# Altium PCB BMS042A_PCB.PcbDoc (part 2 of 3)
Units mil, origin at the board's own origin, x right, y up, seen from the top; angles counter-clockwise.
Board outline 4409.45 x 3307 mil, 6 copper layers (Top Layer, Layer 2 - PGND, Layer 3, Layer 4, Layer 5 - PGND, Bottom Layer), stack 60.8 mil thick; 273 components, 77 nets, 544 pads, 927 vias.
Unrouted connection lines stored in the file: 219.
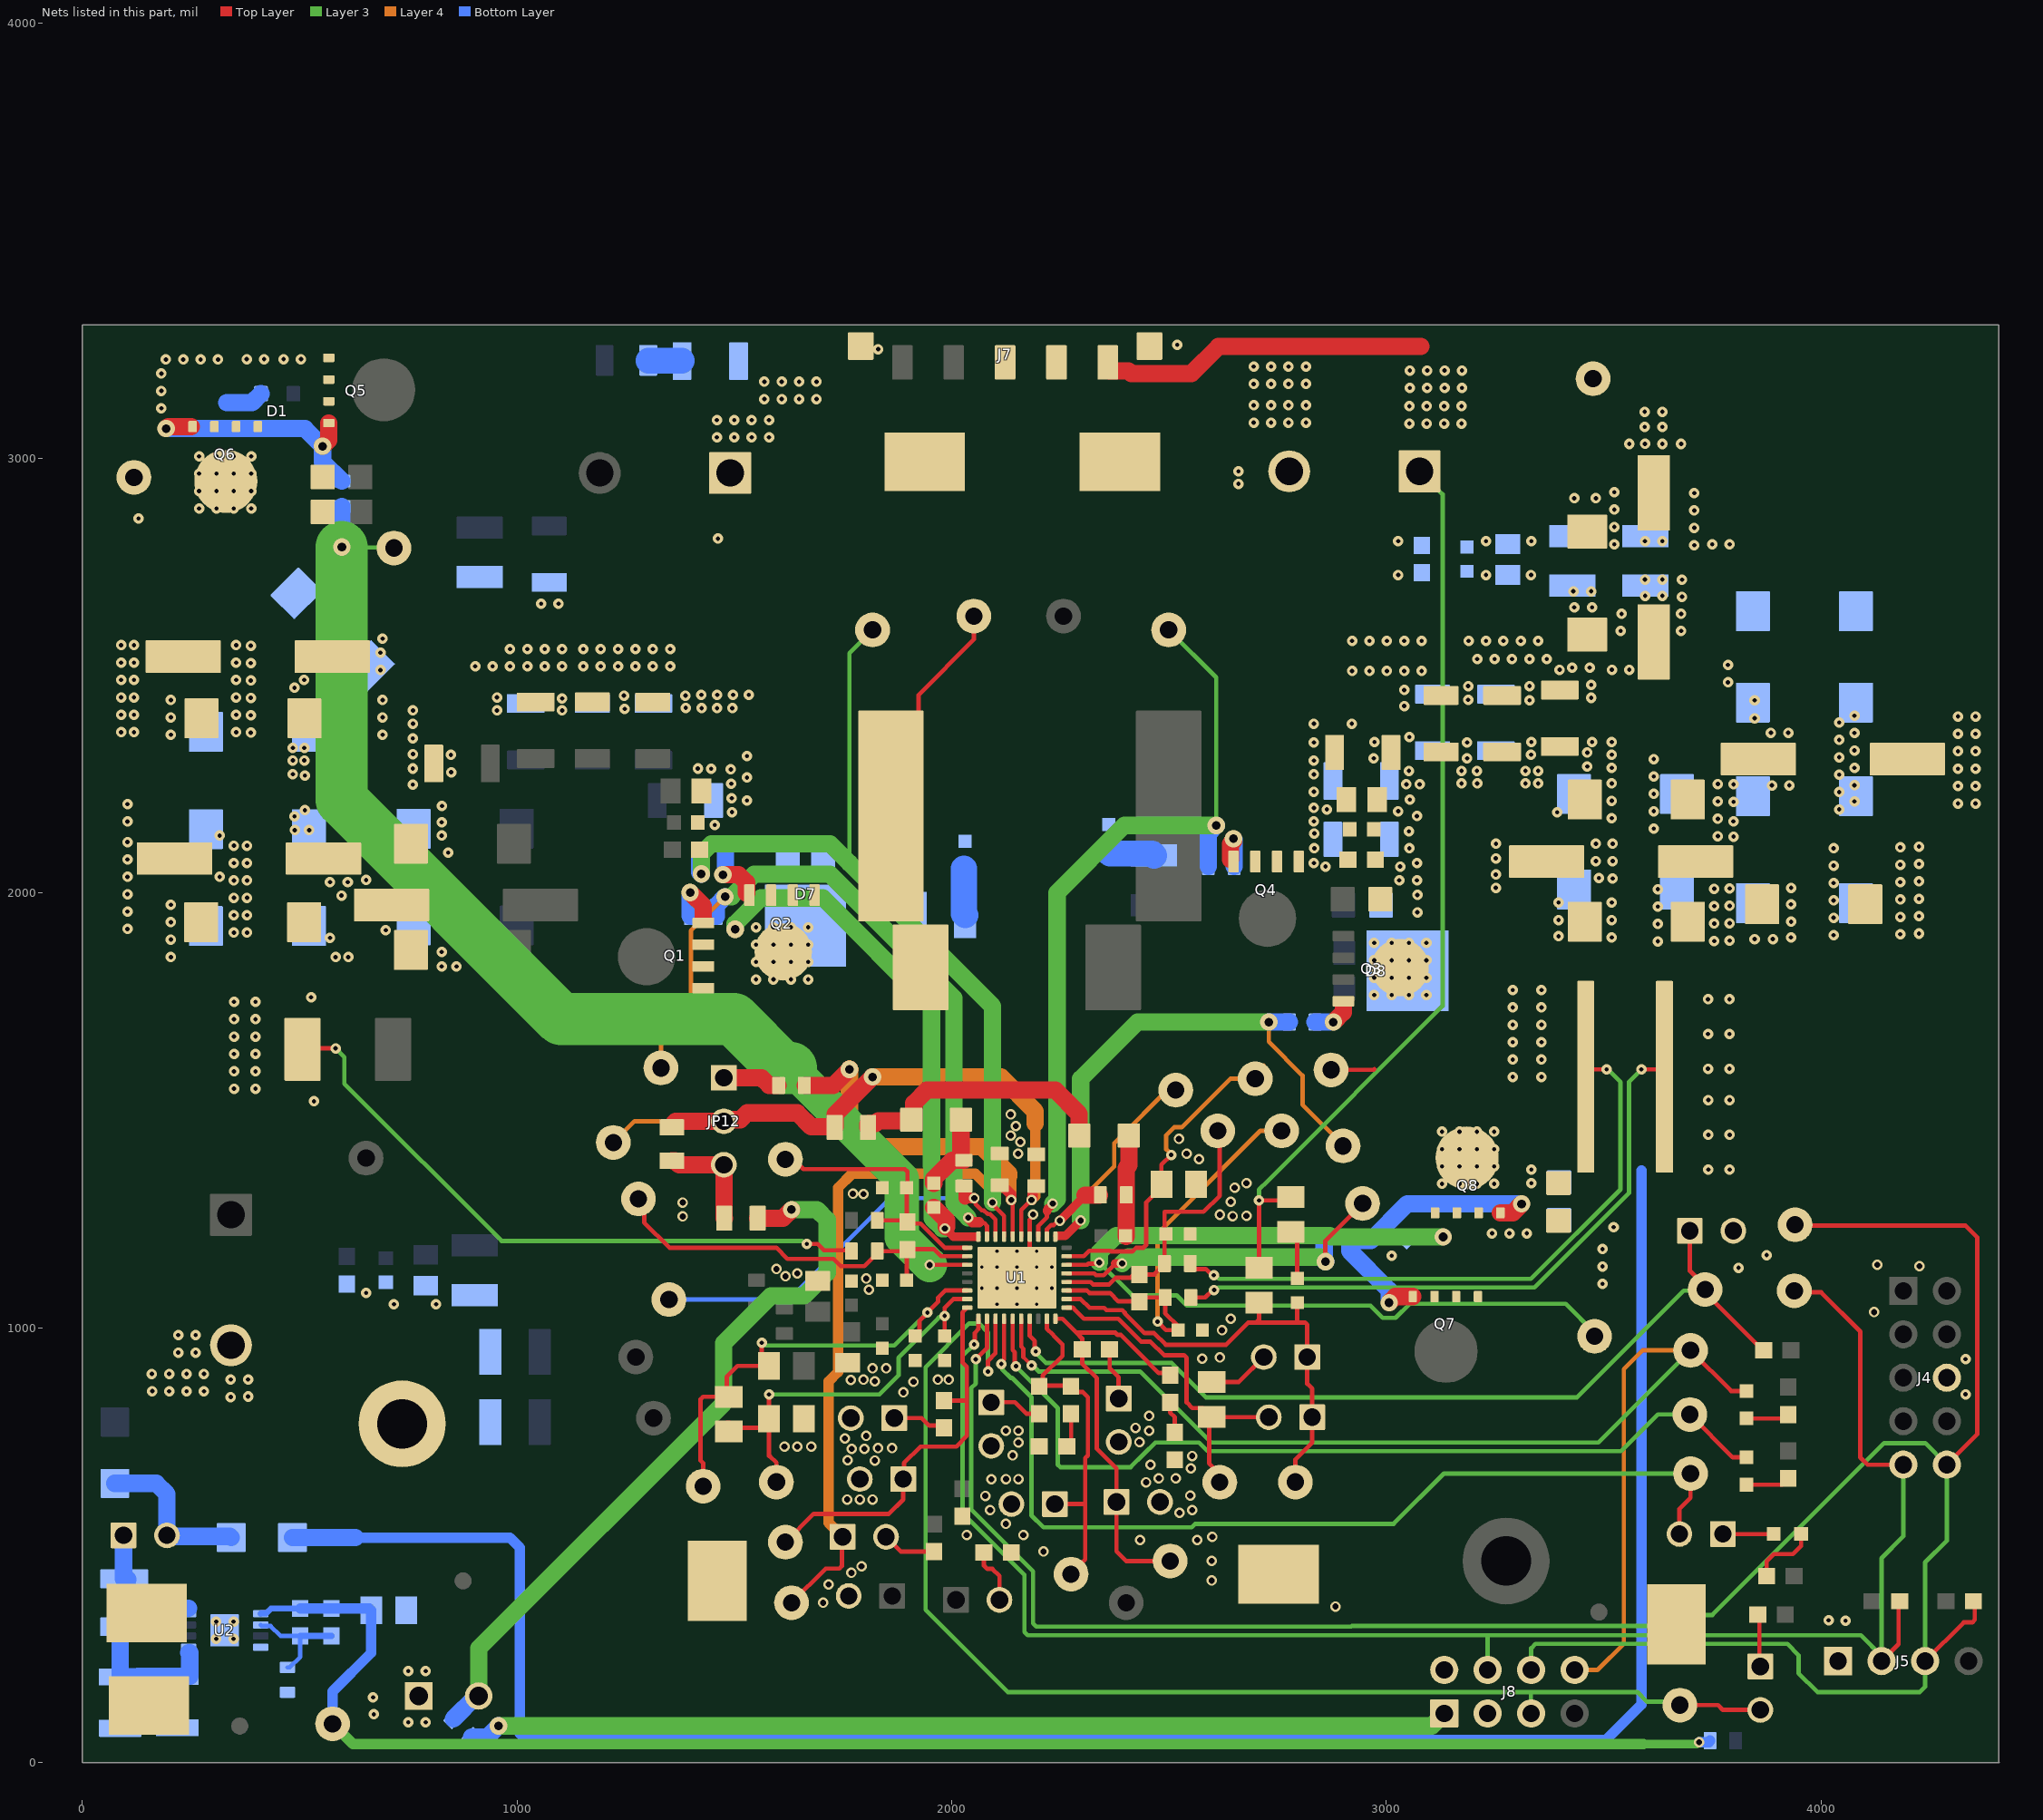
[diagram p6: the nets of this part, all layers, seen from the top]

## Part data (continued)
J7: library part CMP-0097332-1, "Conn Board to Board HDR 5 POS 3mm Solder RA SMD T/R", Current_A=5A, Digikey Part Number=478-109159005101916CT-ND, Manufacturer="KYOCERA AVX", Mouser Part Number=581-109159005101916, Operating Temperature Range="-40°C to +125°C", Voltage_V=125V
J8: library part CMP-0075408-3, "Header, 100mil, 4x2, Gold, TH", Color=Black, Current_A=6.3A, Manufacturer=Samtec, Supplier Part Number 1=SAM1028-04-ND, Voltage_V=550V
JP1 JP2 JP13 JP14 JP15: library part CMP-0002337-1, "Header, 100mil, 2x1, Tin, TH", Color=Black, Current_A=3A, Manufacturer="Sullins Connector Solutions", Supplier Part Number 1=S1012E-02-ND, Voltage_V=1.8kV
JP3 JP4 JP5 JP6 JP7 JP8 JP9 JP10 JP11 JP16: library part CMP-0002337-1, "Header, 100mil, 2x1, Tin, TH", Color=Black, Current_A=3A, Manufacturer="Sullins Connector Solutions", PartNumber=PEC02SAAN, Supplier Part Number 1=S1012E-02-ND, Voltage_V=1.8kV
JP12: library part CMP-0002338-1, "Header, 100mil, 3x1, Tin, TH", Color=Black, Current_A=3A, Manufacturer="Sullins Connector Solutions", Supplier Part Number 1=S1012E-03-ND, Voltage_V=1.8kV
L1: library part CMP-0093259-1, "Commercial Inductors, High Saturation Series 10uH 16.5A 12mΩ 20%", Manufacturer=Vishay, Operating Temperature Range="-55°C to +125°C", Test Frequency=100kHz, Tolerance_%=20%
L2: library part CMP-0096007-1, "Power Choke Coil 10uH 20% 9A 22mOhm", Manufacturer=Cyntec, Operating Temperature Range="-55°C to +125°C", Test Frequency=100kHz, Tolerance_%=20%
LBL1: library part CMP-0003625-1, "Thermal Transfer Printable Labels, 0.650\" W x 0.200\" H - 10,000 per roll", Manufacturer=Brady, Supplier Part Number 1=97C5133
LOGO1: library part CMP-0074835-1, "IEC 61010-1 High Voltage Warning"
LOGO2: library part CMP-0074837-2, "IEC 61010-1 Hot Surface Warning", Manufacturer="Texas Instruments"
LOGO3: library part CMP-0074836-1, "IEC 61010-1 Caution Warning"
LOGO5: library part CMP-0074844-1
LOGO6: library part CMP-0074847-1, "FCC_disclaimer"
LOGO7: library part CMP-0074769-1
Q1 Q2 Q3 Q4: library part CMP-0096839-1, "N-Channel 80 V 18.6A (Ta), 70.6A (Tc) 5W (Ta), 71.4W (Tc) Surface Mount PowerPAK® SO-8", Digikey Part Number=742-SIR880BDP-T1-RE3CT-ND, Drain To Source Breakdown Voltage=80V, Input Capacitace At Vds="2930pF @ 40V", Manufacturer=Vishay, Mouser Part Number=78-SIR880BDP-T1-RE3, Operating Temperature Range="-55°C to +150°C", Power_W=5W, Pulse Drain Current=200A, Typ Forward Diode Voltage=0.74V
Q5 Q6 Q7 Q8: library part CMP-0093242-3, "100V N-Channel MOSFET, DFN5x6-8L, RoHS", Drain To Source Breakdown Voltage=100V, Input Capacitace At Vds="5940pF @ 50V", Manufacturer="Alpha & Omega Semiconductor", Operating Temperature Range="-55°C to +150°C", Power_W=6.2W, Pulse Drain Current=320A, Typ Forward Diode Voltage=0.68V
R2: library part CMP-0096841-1, "Res Metal Strip 2512 0.005 Ohm 1% 1W 110ppm/C Molded SMD SMD Embossed Plastic T/R", Digikey Part Number=WSLG-.005CT-ND, Manufacturer=Vishay, Mouser Part Number=71-WSL25125L000FEA, Octopart Part Number=dd8716d1bbbb0240, Operating Temperature Range="-65°C to +170°C", Power_W=1W, TempCo=110ppm/°C, Tolerance_%=1%
R3 R8 R9 R12 R13 R17 R20 R23 R68 R69 R100 R101 R160: library part CMP-0093629-1, "Thick Film Resistors - SMD 1/10watt ZEROohm Jumper", Manufacturer=Vishay, Operating Temperature Range="-55°C to +155°C", Power=250mW, Power_W=330mW, TempCo=100ppm/°C, Tolerance_%=1%
R5 R6 R22 R25: library part CMP-0093685-1, "RES Thick Film, 10Ω, 1%, 0.1W, 100ppm/°C, 0603", Approved Alternate Part Number=541-1.00HHCT-ND, Manufacturer=Vishay, Operating Temperature Range="-55°C to +155°C", Power=100mW, TempCo=100ppm/°C, Tolerance_%=1%, Voltage=75V
R10: library part CMP-0093410-1, "RES Thick Film, 10Ω, 1%, 0.75W, 100ppm/°C, 1206", Manufacturer="Vishay Dale", Operating Temperature Range="-55°C to +155°C", Power_W=750mW, TempCo=100ppm/°C, Tolerance_%=1%
R14 R15: library part CMP-0015022-3, "RES, 3.30, 1%, 0.75 W, AEC-Q200 Grade 0, 1210", Manufacturer=Vishay-Dale, Power_W=750mW, Supplier Part Number 1=541-3.30DCT-ND, TempCo="100 ppm/C", Tolerance_%=1%, Value2=0.75W, Value_Code=3R30, ValueDisplayed=3.30
R21: library part CMP-0021522-3, "Thick Film Resistors - SMD 1/8Watt 1Mohms 1% Commercial Use", Manufacturer="Vishay / Dale", Power_W=125mW, Supplier Part Number 1=P1.00MCCT-ND, TempCo="100 ppm/C", Tolerance_%=1%, Value2=0.125W, Value_Code=1M00, ValueDisplayed=1.00M
R24: library part CMP-0093177-1, "5 mOhms ±1% 5W Chip Resistor Wide 4320 (11050 Metric), 2043 Current Sense, Moisture Resistant Metal Foil", Digikey Part Number=FCSL110R005FERCT-ND, Manufacturer=Ohmite, Mouser Part Number=588-FCSL110R005FER, Operating Temperature Range="-55°C to +155°C", Power_W=5W, TempCo=50ppm/°C, Tolerance_%=1%
R27: library part CMP-0021561-3, "RES, 133 k, 1%, 0.125 W, AEC-Q200 Grade 0, 0805", Manufacturer=Panasonic, Power_W=125mW, Supplier Part Number 1=P133KCCT-ND, TempCo="100 ppm/C", Tolerance_%=1%, Value2=0.125W, Value_Code=133k
R28: library part CMP-0018933-2, "Thick Film Resistors - SMD 0805 Anti-Surge Res. 0.1%, 249Kohm", Manufacturer=Panasonic, Power_W=125mW, Supplier Part Number 1=RG20P249KBCT-ND, TempCo="25 ppm/C", Tolerance_%=0.1%, Value2=0.125W, Value_Code=249k
R30: library part CMP-0021646-3, "RES, 25.5 k, 1%, 0.125 W, AEC-Q200 Grade 0, 0805", Manufacturer=Panasonic, Power_W=125mW, Supplier Part Number 1=P25.5KCCT-ND, TempCo="100 ppm/C", Tolerance_%=1%, Value2=0.125W, Value_Code=25k5, ValueDisplayed=25.5k
R32: library part CMP-0021666-2, "RES, 3.00 k, 1%, 0.125 W, AEC-Q200 Grade 0, 0805", Manufacturer=Panasonic, Power_W=125mW, Supplier Part Number 1=P3.0KCCT-ND, TempCo="100 ppm/C", Tolerance_%=1%, Value2=0.125W, Value_Code=3k00, ValueDisplayed=3.00k
R34: library part CMP-0023199-5, "RES, 5.23 k, 1%, 0.1 W, 0603", Manufacturer=Yageo, Power_W=100mW, Supplier Part Number 1=311-5.23KHRCT-ND, TempCo="100 ppm/C", Tolerance_%=1%, Value2=0.1W, Value_Code=5k23, ValueDisplayed=5.23k
R36: library part CMP-0022038-4, "RES, 133 k, 1%, 0.1 W, AEC-Q200 Grade 0, 0603", Manufacturer=Vishay-Dale, Power_W=100mW, Supplier Part Number 1=541-133KHCT-ND, TempCo="100 ppm/C", Tolerance_%=1%, Value2=0.1W, Value_Code=133k
R41 R53 R54 R55 R56: library part CMP-0022746-5, "RES, 10.0 k, 1%, 0.1 W, 0603", Manufacturer=Yageo, Power_W=100mW, Supplier Part Number 1=311-10.0KHRCT-ND, TempCo="100 ppm/C", Tolerance_%=1%, Value2=0.1W, Value_Code=10k0, ValueDisplayed=10.0k
R45 R120: library part CMP-0092857-1, "Thick Film Resistors - SMD 1/8watt ZEROohm Jumper", Manufacturer=Vishay, Operating Temperature Range="-55°C to +155°C", Power_W=500mW, TempCo=200ppm/°C, Tolerance_%=5%
R46: library part CMP-0092853-1, "Thick Film Resistors - SMD 3/4watt 20ohms 1% High Power AEC-Q200", Manufacturer="Vishay Dale", Operating Temperature Range="-55°C to +155°C", Part Number=CRCW12104R30FKEAHP, Power_W=750mW, TempCo=100ppm/°C, Tolerance_%=1%
R48: library part CMP-0023140-4, "RES, 499 k, 1%, 0.1 W, 0603", Manufacturer=Yageo, Power_W=100mW, Supplier Part Number 1=311-499KHRCT-ND, TempCo="100 ppm/C", Tolerance_%=1%, Value2=0.1W, Value_Code=499k
R49: library part CMP-0093627-1, "Thick Film Chip Resistors 0603 316kΩ 0.1W 1% 100ppm/°C", Manufacturer=Bourns, Operating Temperature Range="-55°C to +155°C", Power_W=100mW, TempCo=100ppm/°C, Tolerance_%=1%
R50 R51 R52: library part CMP-0022984-5, "RES, 2.21 k, 1%, 0.1 W, 0603", Manufacturer=Yageo, Power_W=100mW, Supplier Part Number 1=311-2.21KHRCT-ND, TempCo="100 ppm/C", Tolerance_%=1%, Value2=0.1W, Value_Code=2k21, ValueDisplayed=2.21k
R59: library part CMP-0020803-2, "RES, 0, 5%, 0.125 W, 0805", Manufacturer="Yageo America", Power_W=125mW, Supplier Part Number 1=311-0.0ARCT-ND, TempCo="200 ppm/C", Tolerance_%=5%, Value2=0.125W, Value_Code=0000, ValueDisplayed=0
R64: library part CMP-0018881-2, "RES, 13.7 k, 0.1%, 0.125 W, 0805", Manufacturer="Susumu Co Ltd", Power_W=125mW, Supplier Part Number 1=RG20P13.7KBCT-ND, TempCo="25 ppm/C", Tolerance_%=0.1%, Value2=0.125W, Value_Code=13k7, ValueDisplayed=13.7k
R65: library part CMP-0023018-5, "RES, 30.1 k, 1%, 0.1 W, 0603", Manufacturer=Yageo, Power_W=100mW, Supplier Part Number 1=311-30.1KHRCT-ND, TempCo="100 ppm/C", Tolerance_%=1%, Value2=0.1W, Value_Code=30k1, ValueDisplayed=30.1k
R66: library part CMP-0022990-5, "RES, 2.49 k, 1%, 0.1 W, 0603", Manufacturer=Yageo, Power_W=100mW, Supplier Part Number 1=311-2.49KHRCT-ND, TempCo="100 ppm/C", Tolerance_%=1%, Value2=0.1W, Value_Code=2k49, ValueDisplayed=2.49k
R67: library part CMP-0082533-1, "RES, 4.99 k, 1%, 0.1 W, 0603", Manufacturer=Vishay-Dale, Power_W=100mW, Supplier Part Number 1=541-3985-1-ND, TempCo="100 ppm/C", Tolerance_%=1%, Value2=0.1W, Value_Code=4k99, ValueDisplayed=4.99k
R151 R152 R153 R154 R400 R401: library part CMP-0083440-1, "RES, 100 k, 5%, 0.5 W, 1210", Manufacturer=Yageo, Power_W=500mW, TempCo="100 ppm/C", Tolerance_%=5%, Value2=0.5W, Value_Code=100k
R200 R201: library part CMP-0025898-5, "RES, 1.8 k, 5%, 0.1 W, 0603", Manufacturer=Yageo, Power_W=100mW, Supplier Part Number 1=311-1.8KGRCT-ND, TempCo="100 ppm/C", Tolerance_%=5%, Value2=0.1W, Value_Code=1k80, ValueDisplayed=1.8k
R300: library part CMP-0092857-1, "Thick Film Resistors - SMD 1/2watt 1.5ohms 1% High Power AEC-Q200", Manufacturer=Vishay, Operating Temperature Range="-55°C to +155°C", Power_W=500mW, TempCo=200ppm/°C, Tolerance_%=5%
R1000 R1001 R1002 R1003 R1004 R1005: library part CMP-0096818-1, "0 Ohms Jumper 0.245W Chip Resistor 0805 (2012 Metric) - Metal Element", Digikey Part Number=JR0805X35ECT-ND, Manufacturer=Ohmite, Mouser Part Number=588-JR0805X35E, Operating Temperature Range="-55°C to +150°C", Power_W=245mW
SH-JP1 SH-JP2 SH-JP3 SH-JP4 SH-JP5 SH-JP6 SH-JP7 SH-JP8 SH-JP9 SH-JP10 SH-JP11: library part CMP-0003623-3, "Shunt, 100mil, Gold plated, Black", Alternate Manufacturer=3M, Alternate PartNumber=969102-0000-DA, Manufacturer=Samtec, Supplier Part Number 1=SAM8858-ND
TP1 TP2 TP3 TP4 TP5 TP6 TP7 TP8 TP9 TP10 TP11 TP12 TP13 TP14 TP15 TP16 TP17 TP18 TP19 TP20 TP21 TP22 TP23 TP24 TP25 TP26 TP27 TP28 TP29 TP30 TP31 TP32 TP33 TP34 TP41 TP42 TP43 TP44 TP45 TP46: library part CMP-0055139-1, "Test Point, Miniature, White, TH", Color=White, Manufacturer=Keystone, Supplier Part Number 1=36-5002-ND
TP35 TP36 TP37 TP38 TP39 TP40 TP47: library part CMP-0055153-1, "Test Point, Compact, SMT", Manufacturer=Keystone, Supplier Part Number 1=36-5016TR-ND
U1: library part CMP-0091286-5, "Standalone/I2C Controlled, 70V, 20A Buck-Boost Multi-Chemistry Battery Charge Controller", Manufacturer="Texas Instruments", Max Supply Voltage=70V, Min Supply Voltage=4.2V, Operating Temperature Range="-40°C to +125°C", Output Voltage=0-60V
U2: library part CMP-0093068-2, "Linear Voltage Regulator IC Positive Adjustable 1 Output 50mA 8-MSOP-EP", Digikey Part Number=LT3010EMS8E#PBF-ND, Dropout Voltage=300mV, Manufacturer="Analog Devices", Max Supply Voltage=80V, Min Supply Voltage=3V, Mouser Part Number=584-LT3010EMS8E#PBF, Nominal Supply Current=30-1800uA, Operating Temperature Range="-40°C to +125°C", Output Voltage=1.275-60V, Part Number=LT3010EMS8E-PBF
ZZ1: library part CMP-0077236-1
ZZ2: library part CMP-0077237-1
ZZ3: library part CMP-0077238-1
ZZ4 ZZ5 ZZ6 ZZ7: library part CMP-0077238-1, "These assemblies must comply with workmanship standards IPC-A-610 Class 2, unless otherwise specified."

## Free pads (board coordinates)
  round 200 hole 114.17 mask+1.97: Pad1(3275.32,463.57) Pad2(736,779)

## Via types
v1: diameter 24, hole 10, Top Layer to Bottom Layer, tented both sides, 653 vias
v2: diameter 24, hole 9.8, Top Layer to Bottom Layer, tented both sides, 132 vias
v3: diameter 24, hole 14, Top Layer to Bottom Layer, tented both sides, 105 vias
v4: diameter 40, hole 20, Top Layer to Bottom Layer, tented both sides, 21 vias
v5: diameter 19.68, hole 7.87, Top Layer to Bottom Layer, tented both sides, 16 vias

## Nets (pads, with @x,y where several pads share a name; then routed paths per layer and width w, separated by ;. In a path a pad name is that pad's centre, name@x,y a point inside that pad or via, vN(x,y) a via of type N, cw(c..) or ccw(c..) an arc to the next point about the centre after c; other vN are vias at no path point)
3V3_PULLUP: C48.1 C50.1 R48.2 R69.1 TP32.1 U2.1 | length 3756.5
  Layer 3 w20: 3591.45,42.45 3591.58,42.32 3713.47,42.32 3717.92,46.76 v3(3719,46.76)
  Layer 3 w24: TP32.1@576,89 622.55,42.45 3591.45,42.45
  Bottom Layer w14: U2.1@410.51,342.17 411.78,343.44 423.39,343.44 434.32,354.38 460.88,354.38 R48.2@501.51,354.38 ; C48.1@660.62,354.38 C48.1@665,350
  Bottom Layer w24: R48.2@501.51,354.38 C48.1@660.62,354.38 ; TP32.1@572,92 TP32.1@576,96 ; TP32.1@576,89 TP32.1@576,96 ; C48.1@665,350 665,252.47 576,163.47 TP32.1@576,96 ; v3(3719,46.76) 3741.71,46.76 3744.47,49.53 R69.1@3744.47,50.37
/CE: JP13.1 R56.1 TP21.1 U1.7 | length 2115.1
  Top Layer w9.84: U1.7@2179.55,1020.76 2179.55,980.95 2190.87,969.63 2190.87,948.55 v1(2193.58,945.84)
  Top Layer w10: JP13.1@3698,1223 3698,1130.78 3733,1095.78 TP21.1@3733,1088 3733,1081.52 3866.52,948 R56.1@3867.5,948
  Layer 3 w10: v1(2193.58,945.84) 2193.58,942.05 2216.3,919.33 2505.53,919.33 2585.32,839.53 3437.97,839.53 3683.86,1085.42 3730.42,1085.42 TP21.1@3733,1088
/INT: J8.5 JP14.2 TP30.1 U1.3 | length 3044.9
  Top Layer w9.84: v1(2083.46,899.33) 2083.46,923.64 2100.81,940.99 U1.3@2100.81,1020.76
  Top Layer w10: TP30.1@3678.5,135.5 TP30.1@3675,132 3763,132 3774,121 JP14.2@3860,121 ; JP14.2@3854.5,135.5 JP14.2@3858,139
  Layer 3 w10: v1(2083.46,899.33) 2083.46,989.34 2062.85,1009.95 2040.61,1009.95 1939.97,909.3 1939.97,351.18 2129.15,162 3332.47,162 ; J8.5@3333,113 3332.47,113.53 3332.47,162 ; TP30.1@3675,132 3667.16,139.84 3599.12,139.84 3576.96,162 3332.47,162
/PG: D6.1 J8.8 TP9.1 U1.6 | length 2902.7
  Top Layer w9.84: U1.6@2159.86,1020.76 2159.86,956.71 2164.79,951.79 2164.79,932.59 2183.56,913.82 v1(2183.56,913.52)
  Top Layer w10: TP9.1@3699.5,948 3793,854.5 D6.1@3828,854.5
  Layer 3 w10: v1(2183.56,913.52) 2186.23,913.52 2200.26,899.49 2433.21,899.49 2596.81,735.89 3487.39,735.89 TP9.1@3699.5,948
  Layer 4 w10: J8.8@3433,213 3485.64,213 3545.95,273.3 3545.95,905.13 3588.81,948 TP9.1@3699.5,948
AC_OUT: C7.2 C44.2 C500.2 C501.2 C508.2 C509.2 C510.2 C512.2 Q6.5-6-7-8 R2.1 R5.2 R1000.2 R1001.2 TP45.1 | length 1492.9
  Top Layer w10: R2.1@506.69,1640.5 509,1642.82 v1(582.78,1642.82) ; v1(1666.85,1192.79) 1691.61,1192.79 1706,1178.4 1767.44,1178.4 R5.2@1769.58,1176.27
  Layer 3 w10: v1(582.78,1642.82) 603.16,1622.44 603.16,1561.28 964.65,1199.79 1656.07,1199.79 1663.06,1192.79 v1(1666.85,1192.79)
  other v1: 533.1,1521 349.32,1549.77 398.57,1549.77 349.32,1589.77 398.57,1589.77 349.32,1629.77 398.57,1629.77 349.32,1669.77 398.57,1669.77 349.32,1709.77 398.57,1709.77 349.32,1749.77 398.57,1749.77 526.36,1759.99 204,1852.53 204,1893 348.82,1909.01 379.24,1909.01 104,1917.3 204,1933 348.82,1949.01 379.24,1949.01 104,1957.3 204,1973 348.82,1989.01 379.24,1989.01 104,1997.3 348.82,2029.01 379.24,2029.01 104,2037.3 316.07,2037.3 348.82,2069.01 379.24,2069.01 104,2077.3 348.82,2109.01 379.24,2109.01 104,2117.3 316.07,2132 104,2164.4 104,2204.4 204,2364 387.86,2368.86 89.43,2370 119,2370 354,2370 204,2404 387.86,2408.86 89.43,2410 119,2410 354,2410 204,2444 387.86,2448.86 89.43,2450 119,2450 354,2450 387.86,2488.86 89.43,2490 119,2490 354,2490 387.86,2528.86 89.43,2530 119,2530 354,2530 387.86,2568.86 89.43,2570 119,2570 354,2570 129.32,2861.41
  other v2: 268.82,2884.5 308.82,2884.5 348.82,2884.5 388.82,2884.5 268.82,2924.5 308.82,2924.5 348.82,2924.5 388.82,2924.5 268.82,2964.5 308.82,2964.5 348.82,2964.5 388.82,2964.5 268.82,3004.5 308.82,3004.5 348.82,3004.5 388.82,3004.5
ACDRV: R12.1 TP4.1 U1.31 | length 2755.5
  Top Layer w9.84: v3(1949.19,1144.53) 1949.43,1144.77 U1.31@2035.85,1144.77
  Layer 3 w10: v4(597.22,2795.71) 598.26,2794.67 716.01,2794.67 TP4.1@717.06,2793.63
  Layer 3 w80: 1630.07,1597.65 1885.32,1342.4 1885.32,1208.41 v3(1949.19,1144.53)
  Layer 3 w120: v4(597.22,2795.71) 597.22,2213.78 1101.23,1709.77 1499.06,1709.77 1611.18,1597.65 1630.07,1597.65
  Bottom Layer w40: v4(597.22,2795.71) R12.1@597.22,2888.47
ACN: C11.1 C34.2 R6.1 TP11.1 U1.29 | length 640.8
  Top Layer w9.84: 1984.07,1184.14 U1.29@2035.85,1184.14
  Top Layer w10: TP11.1@1617.5,1387.5 1636.44,1387.5 1658.94,1365 1892.46,1365 1898.32,1359.14 1898.32,1323.86 C11.1@1896.45,1321.99 C34.2@1896.45,1244.91 ; R6.1@1828.64,1247 1894.35,1247 C34.2@1896.45,1244.91 ; 1984.07,1184.22 1983.89,1184.22 1928.49,1239.62 1901.74,1239.62 C34.2@1898.32,1243.04 C34.2@1896.45,1244.91
ACOV: C32.1 R27.1 R30.2 TP14.1 U1.35 | length 939.9
  Top Layer w9.84: 1990.89,1053.19 2003.73,1066.03 U1.35@2035.85,1066.03
  Top Layer w10: R27.1@1482.45,781.19 R27.1@1488.95,781.19 ; R27.1@1487.48,761.19 1496.13,769.84 R30.2@1579.96,769.84 ; v1(1579.96,846.62) R30.2@1579.96,790.63 R30.2@1579.96,769.84 ; TP14.1@1596.8,645.13 1596.8,690 1581.63,705.17 1579.96,705.17 R30.2@1579.96,769.84 ; C32.1@1983.89,981.03 v1(1983.89,1027.5) 1983.89,1046.2 1990.89,1053.19
  Layer 3 w10: v1(1579.96,846.62) 1833.95,846.62 1877.84,890.52 1877.84,930.96 1970.05,1023.16 1971.71,1024.82 1981.21,1024.82 v1(1983.89,1027.5)
ACP: C10.1 C34.1 R5.1 TP10.1 U1.30 | length 953.8
  Top Layer w9.84: 1975.91,1164.46 U1.30@2035.85,1164.46
  Top Layer w10: TP10.1@1279.4,1296.53 1292.79,1283.13 1292.79,1242.05 1350.71,1184.14 1596.8,1184.14 1622.38,1158.56 1728.14,1158.56 1744.96,1141.74 1799.03,1141.74 1828.64,1171.35 R5.1@1828.64,1176.27 1894.54,1176.27 C34.1@1896.45,1178.18 ; TP10.1@1294.4,1303.39 TP10.1@1307.79,1289.99 ; C10.1@1896.45,1113.97 C34.1@1896.45,1178.18 ; 1975.91,1164.53 1975.52,1164.53 1958.93,1181.12 1899.39,1181.12 C34.1@1896.45,1178.18
ACUV: C20.1 R21.1 R27.2 TP13.1 U1.34 | length 1083.6
  Top Layer w9.84: C20.1@1915.76,981.03 1925.84,991.11 1925.84,1015.48 1944.04,1033.68 v1(1944.04,1035.12) ; v1@1944.04,1039.58 1948.5,1039.58 1968.79,1059.87 1968.79,1069.88 1984.63,1085.72 U1.34@2035.85,1085.72
  Top Layer w10: TP13.1@1428.34,635.59 1428.34,688.82 1422.5,694.66 1422.5,835.35 1428.34,841.19 R27.2@1487.48,841.19 1482.45,846.23 1482.45,887.05 1507.47,912.07 R21.1@1579.96,912.07 1563.1,928.94 v1(1563.1,965.65)
  Layer 3 w10: v1(1563.1,965.65) 1566.89,965.65 1573.31,959.22 1868.14,959.22 v1(1944.04,1035.12)
BAT: C24.1 C31.1 C38.2 C39.2 C78.1 C506.2 C507.2 C516.2 C517.2 C518.2 C519.2 D9.2 J3.1 J7.1 R24.1 R25.1 R28.2 R59.2 R400.2 R401.2 TP3.1 | length 9144
  Top Layer w10: R25.1@2550.21,1069.88 2582.97,1069.88 2599.97,1086.88 v1(2603.76,1086.88) ; R28.2@2707.04,1138.12 v1(2707.04,1293.06) 2772.65,1293.06 R59.2@2780.2,1300.61 ; v1(3586.31,1594.14) 3624.9,1594.14 3639.59,1579.45 R24.1@3639.59,1577.28
  Top Layer w40: J7.1@2359.13,3220.53 2359.13,3204.78 2362.76,3201.16 2406.97,3201.16 2413.51,3194.62 2551.46,3194.62 2613.84,3257 3079.27,3257
  Layer 3 w10: v1(2603.76,1086.88) 2607.54,1086.88 2613.27,1092.61 3340.69,1092.61 3558.39,1310.31 3558.39,1566.22 v1(3586.31,1594.14) ; v1(2707.04,1293.06) 2707.04,1317.71 2727.06,1337.73 2727.18,1337.73 3129.33,1739.88 3129.33,2917.15 J3.1@3076.42,2970.06
  Bottom Layer w24: 628.5,517.5 983.44,517.5 1007.07,493.87 1007.07,66.06 1021.13,52 3505,52 3586.31,133.31 3586.31,1361.61
  Bottom Layer w40: D9.2@483.44,517.5 628.5,517.5
  other v1: 3740.36,1363.83 3789.62,1363.83 3740.36,1443.83 3789.62,1443.83 3740.36,1523.83 3789.62,1523.83 3739.82,1595.78 3789.08,1595.78 3739.82,1675.78 3789.08,1675.78 3739.82,1755.78 3789.08,1755.78 4028.57,1903 4182.02,1905 4224.93,1906.69 4028.57,1943 4182.02,1945 4224.93,1946.69 4028.57,1983 4182.02,1985 4224.93,1986.69 4028.57,2023 4182.02,2025 4224.93,2026.69 4028.57,2063 4182.02,2065 4224.93,2066.69 4028.57,2103 4182.02,2105 4224.93,2106.69 4041.57,2192.16 4314.57,2206 4355,2206 4076.57,2210.65 4041.57,2232.16 4314.57,2246 4355,2246 4076.57,2248 4041.57,2272.16 4314.57,2286 4355,2286 4076.57,2288 4041.57,2312.16 4314.57,2326 4355,2326 4076.57,2328 4041.57,2352.16 4314.57,2366 4355,2366 4076.57,2368 4041.57,2392.16 4314.57,2406 4355,2406 4076.57,2408 3708,2800 3524.03,2802 3749.5,2802 3789.5,2802 3027,2809.31 3229.08,2809.31 3333.29,2809.31 3594.69,2809.31 3634.69,2809.31 3708,2840 3524.03,2842 3708,2880 3524.03,2882 3432,2908 3481.96,2908 3708,2920 3524.03,2922 3558.51,3033.05 3594.69,3033.18 3634.69,3033.05 3678,3033.05 3594,3072 3634.69,3072 3052.82,3079.91 3092.82,3079.91 3132.82,3079.91 3172.82,3079.91 3594,3107 3634.69,3107 3052.82,3119.91 3092.82,3119.91 3132.82,3119.91 3172.82,3119.91 3053.82,3161.91 3093.82,3161.91 3133.82,3161.91 3173.82,3161.91 3053.82,3201.91 3093.82,3201.91 3133.82,3201.91 3173.82,3201.91
BAT_DRV: R9.2 TP5.1 U1.15 | length 824.8
  Top Layer w9.84: U1.15@2264.2,1125.09 2327.66,1125.09
  Top Layer w10: 2327.66,1125.09 2331.76,1120.99 2349.69,1120.99 2376.54,1147.83 ; v4@2859.48,1165.83 2859.48,1200.18 TP5.1@2945.3,1285.99
  Top Layer w20: 2376.54,1147.83 v3@2391.96,1147.83
  Layer 3 w40: v3(2392.07,1147.83) 2406.8,1162.55 2849.22,1162.55 v4(2859.75,1152.03)
  Bottom Layer w40: R9.2@2856.73,1201.2 2856.73,1155.04 v4(2859.75,1152.03)
BAT_SRC: C36.2 Q7.1 Q7.2 Q7.3 Q8.1 Q8.2 Q8.3 R1004.2 R1005.2 TP6.1 U1.16 | length 2151
  Top Layer w9.84: U1.16@2264.2,1144.77 2277.61,1144.77 2311.27,1144.77 2311.62,1145.12
  Top Layer w10: 2311.27,1144.85 2312.08,1144.85 2314.8,1147.57 2336.92,1147.57 v3(2339.6,1150.25)
  Layer 3 w10: v3(2339.6,1150.25) 2415.13,1074.72 2517.26,1074.72 2540.8,1051.18 2963.38,1051.18 2991.64,1022.92 3021.02,1022.92 3053.41,1055.31 3396.9,1055.31 3397,1055.21 3412.2,1055.21 3478.82,988.58 TP6.1@3478.82,980.4
  Layer 3 w40: v3(2339.6,1150.25) 2339.6,1173.5 2378.49,1212.39 2869.87,1212.39 2873.34,1208.92 v4(3130.46,1208.92)
  other v1: 3496.99,1101.11 3496.99,1141.11 3011.93,1165.83 3496.99,1181.11 3242.88,1217.02 3282.88,1217.02 3322.88,1217.02 3522.65,1231.61
BTST1: R13.1 TP26.1 U1.26 | length 990.2
  Top Layer w9.84: 2069,1270.15 2073.95,1270.15 2082.72,1261.38 2088.5,1261.38 2100.81,1249.07 U1.26@2100.81,1209.73
  Top Layer w10: v3(2051.97,1298.12) 2054.64,1295.44 2054.64,1284.5 2069,1270.15
  Top Layer w24: R13.1@2028.2,1326.16 R13.1@2030.92,1323.44 ; 2030.92,1298.12 v3(2051.97,1298.12)
  Top Layer w30: 2030.92,1298.12 R13.1@2030.92,1323.44
  Bottom Layer w10: TP26.1@1333.1,1054.17 TP26.1@1341.09,1054.17 ; TP26.1@1349.61,1064.95 1625.61,1064.95 1858.79,1298.12 v3(2051.97,1298.12) ; TP26.1@1352.63,1099.85 TP26.1@1365.48,1087
BTST2: R23.1 TP28.1 U1.20 | length 596.5
  Top Layer w9.84: U1.20@2218.92,1209.73 2218.92,1226.5 2228.72,1236.31 2234.9,1236.31 2245.02,1246.42 v3(2248.85,1246.42) ; v3@2246.28,1248.99 v3@2251.42,1248.99
  Top Layer w10: v3(2248.85,1246.42) v3@2251.42,1248.99
  Top Layer w20: v3@2251.42,1248.99 2307.09,1304.66
  Top Layer w24: R23.1@2339.6,1304.66 2340.56,1305.62 R23.1@2342.36,1305.62
  Top Layer w40: 2307.09,1304.66 R23.1@2339.6,1304.66
  Layer 4 w10: v3(2248.85,1246.42) 2249.46,1246.42 2373.81,1370.77 2373.81,1424.57 TP28.1@2506.82,1557.58
DRV_SUP: C26.1 JP12.2 R120.2 R300.2 TP15.1 U1.23 | length 1571
  Top Layer w9.84: U1.23@2159.86,1209.73 2159.86,1270.99 2183.12,1294.24 v3(2183.56,1294.24)
  Top Layer w10: R300.2@1362.06,1471.75 R300.2@1365.27,1468.54
  Top Layer w24: v3(2183.56,1294.24) 2185.94,1296.63 2185.94,1322.31 2189.69,1326.05 C26.1@2194.61,1326.05
  Top Layer w40: R300.2@1362.06,1471.75 1365.31,1475 JP12.2@1476,1475 1479.65,1478.65 1513.79,1478.65 1529.31,1494.16 1644.93,1494.16 1676.77,1462.32 1729.45,1462.32 1730.75,1461.02 R120.2@1730.75,1460.93 1732.05,1462.23 1732.05,1491.05 v4(1818,1577)
  Layer 4 w10: TP15.1@1221.64,1426.18 1270.46,1475 JP12.2@1476,1475
  Layer 4 w24: v3(2183.56,1294.24) 2192.08,1302.77 2192.08,1469.92
  Layer 4 w40: v4(1818,1577) 2113,1577 2192.08,1497.92 2192.08,1469.92
EXT_DRV: J6.2 R45.1 R68.2 | length 1729.9
  Top Layer w40: R45.1@1553.76,1252.02 1612,1252.02 v4(1631.64,1271.66)
  Layer 3 w40: J6.2@911.9,153 911.9,262.47 1475.63,826.2 1475.63,964.79 1583.9,1073.07 1660.07,1073.07 1713.85,1126.85 1713.85,1248.23 1690.42,1271.66 v4(1631.64,1271.66)
  Bottom Layer w40: R68.2@853.87,100.15 906.71,153 J6.2@911.9,153
FB: C25.2 JP1.1 JP2.1 R28.1 TP24.1 U1.12 | length 1122.4
  Top Layer w9.84: U1.12@2264.2,1066.03 2296.84,1066.03 2317.1,1045.77
  Top Layer w10: 2317.1,1045.77 2350.51,1045.77 2355.68,1040.6 2392.48,1040.6 2398.34,1034.74 2398.34,1033.7 2444.21,987.83 2465.59,987.83 2492.5,960.92 2631.11,960.92 2682.31,1012.12 2794.93,1012.12 ; 2702.18,1013.83 2707.04,1018.69 R28.1@2707.04,1058.12 ; TP24.1@2790.6,645.13 2790.6,697.14 2829.35,735.89 JP2.1@2829.35,794.25 2829.35,859.69 2817.87,871.17 JP1.1@2817.87,932.59 2817.87,1006.97 2812.72,1012.12 2794.93,1012.12 ; C25.2@2794.93,1057.69 2794.93,1012.12 ; JP1.1@2799.74,931.71 JP1.1@2802.24,929.21 ; JP2.1@2804.99,816.4 2806.24,815.15 JP2.1@2806.24,797.25 ; JP2.1@2811.21,797.25 JP2.1@2813.71,794.75
FBG: JP2.2 R64.1 TP42.1 U1.11 | length 796.8
  Top Layer w9.84: U1.11@2264.2,1046.35 2278.83,1046.35 2285.6,1039.58
  Top Layer w10: 2285.6,1039.56 2304.4,1020.76 2383.22,1020.76 2435.99,967.99 2457.37,967.99 2488.49,936.87 2534.41,936.87 2540.26,931.01 2540.26,828.53 2553.44,815.35 2577.98,815.35 R64.1@2597.98,795.35 ; TP42.1@2616.61,644.7 2616.61,663.64 2592.07,688.18 2592.07,789.45 R64.1@2597.98,795.35 ; JP2.2@2729.35,794.25 2608.43,794.25 2603.76,789.58 R64.1@2597.98,795.35
FSW_SYNC: JP8.1 R36.2 TP16.1 U1.36 | length 923.9
  Top Layer w9.84: 2024.89,994.22 2024.89,1035.39 U1.36@2035.85,1046.35
  Top Layer w10: TP16.1@1617.5,506.86 1682.64,572 1855.56,572 1888.66,605.1 JP8.1@1888.66,651.96 1890.37,653.67 1890.37,688.82 1928.31,726.76 2010.62,726.76 2035.13,751.27 2035.13,832.09 ; R36.2@1982.27,832.69 2034.53,832.69 2035.13,832.09 ; 2024.89,994.22 2024.89,920.35 2035.13,910.12 2035.13,832.09
HIDRV1: R8.2 TP25.1 U1.27 | length 1801.7
  Top Layer w9.84: 2062.87,1243.38 2065.72,1240.53 2075.36,1240.53 2081.12,1234.77 U1.27@2081.12,1209.73
  Top Layer w24: v3(2037.87,1253.04) 2047.53,1243.38 2062.87,1243.38
  Layer 3 w40: v4(1478.64,1991.46) 1493.85,1991.46 1545.57,2043.18 1720.01,2043.18 2005,1758.19 2005,1285.91 v3(2037.87,1253.04)
  Layer 4 w10: TP25.1@1334.8,1620.85 1344.61,1611.04 TP25.1@1331.21,1597.65 1331.21,1674.62 1400.23,1743.63 1400.23,1913.04 v4(1478.64,1991.46)
  Bottom Layer w40: R8.2@1458.05,1946.44 1458.05,1970.87 v4(1478.64,1991.46)
HIDRV2: R3.2 TP27.1 U1.19 | length 1283
  Top Layer w20: 2243.68,1211.54 2261.63,1211.54 v3(2296.71,1246.62)
  Layer 3 w40: v3(2296.71,1246.62) 2296.71,1572.35 2427.36,1703 v4(2729.35,1703)
  Layer 4 w10: v4(2729.35,1703) 2729.35,1657.76 2807,1580.12 2807,1513 2900.2,1419.8 TP27.1@2900.2,1418.18
  Bottom Layer w40: v4(2729.35,1703) R3.2@2776.71,1703
ICHG: JP3.1 R67.2 R201.2 TP17.1 U1.9 | length 818.6
  Top Layer w9.84: U1.9@2218.92,1020.76 2218.92,998.13 2233.95,983.1
  Top Layer w10: 2233.95,983.1 2233.95,982.56 2254.86,961.65 2254.86,935.65 2209.39,890.18 2209.39,880.55 2195.69,866.85 2268.04,866.85 R201.2@2268.04,865.87 ; JP3.1@2237.34,594.5 2306.98,594.5 2307.09,594.4 ; R201.2@2274.6,865.44 2287.57,852.47 2301.23,852.47 2313.22,840.48 2313.22,706.32 2307.09,700.18 2307.09,594.4 ; TP17.1@2284.51,433.15 TP17.1@2274.6,433.15 2274.6,434.6 2306.98,466.98 2306.98,478.33 2307.09,478.44 2307.09,594.4
ILIM_HIZ: JP11.1 R66.2 R200.2 TP7.1 U1.10 | length 992.6
  Top Layer w9.84: U1.10@2238.6,1020.76 2254.86,1020.76
  Top Layer w10: 2254.86,1020.76 2286.93,988.68 ; R200.2@2501.47,890.18 R200.2@2502.47,891.19 2497.61,896.05 2476.55,896.05 2428.93,943.67 2389.09,983.5 2381.65,983.5 2376.48,988.68 2286.93,988.68 ; TP7.1@2502.47,463.57 2401.38,463.57 2379.24,485.7 JP11.1@2379.24,599.34 2379.24,676.35 2333.89,721.7 2333.89,883.96 2300.27,917.58 R66.2@2300.27,949.96 2300.27,975.34 2286.93,988.68
LODRV1: R20.1 TP43.1 U1.25 | length 2033.8
  Top Layer w9.84: U1.25@2120.49,1209.73 2120.49,1257.45
  Top Layer w10: v3(2093.81,1288.14) 2093.81,1284.35 2100.81,1277.35 2100.81,1277.02 2120.38,1257.45
  Layer 3 w10: 1764.67,2069.01 1764.67,2551.86 TP43.1@1818,2605.19
  Layer 3 w40: v4(1424.04,2043.72) 1424.04,2090.09 1447.47,2113.52 1720.16,2113.52 1764.67,2069.01 2093.81,1739.87 v3(2093.81,1288.14)
  Bottom Layer w40: R20.1@1420.47,2096 1420.47,2047.28 v4(1424.04,2043.72)
LODRV2: R17.1 TP44.1 U1.21 | length 1835.6
  Top Layer w9.84: U1.21@2199.23,1209.73 2199.23,1234.66 2219.18,1254.6 2219.18,1268.14
  Top Layer w20: 2219.18,1268.14 2219.18,1271.35 2232.49,1284.66 v3(2232.49,1285.74)
  Layer 3 w10: TP44.1@2499.14,2605.19 2608.41,2495.91 v4(2608.41,2155.29)
  Layer 3 w40: v3(2232.49,1285.74) 2242.49,1295.74 2242.49,2000.67 2397.1,2155.29 v4(2608.41,2155.29)
  Bottom Layer w40: R17.1@2590.44,2061.1 2590.44,2137.31 v4(2608.41,2155.29)
MODE: R32.2 TP20.1 U1.17 | length 744.7
  Top Layer w9.84: U1.17@2264.2,1164.46 2280.97,1164.46 2303.73,1164.46 2316.29,1177.02 2365.29,1177.02 2366.82,1175.49 2415.82,1175.49 2424.47,1184.14 2441.09,1184.14
  Top Layer w10: 2441.09,1184.14 2447.19,1190.24 2447.19,1288.19 2482.5,1323.5 R32.2@2482.5,1330 2482.5,1375 v1(2505,1397.5)
  Layer 4 w10: v1(2505,1397.5) 2505,1398.81 2493.45,1410.36 2493.45,1443.22 2511.38,1461.16 2529.07,1461.16 2640.75,1572.84 TP20.1@2698.25,1572.84 ; TP20.1@2711.17,1596.51 TP20.1@2717.96,1603.3
NetC9_1: C9.1 D1.1 Q5.1 Q5.2 Q5.3 Q6.1 Q6.2 Q6.3 | length 86.5
  Bottom Layer w40: C9.1@333,3128 390.78,3128 D1.1@411.09,3148.31
  other v1: 182,3115 182,3155 182,3195 192.54,3227.16 232.54,3227.16 272.54,3227.16 312.54,3227.16 378.32,3228 418.32,3228 463.16,3228 503.16,3228
NetC9_2: C9.2 D1.3 Q5.4 Q6.4 R12.2 | length 594
  Top Layer w40: v4(193,3068.28) 197.69,3072.97 Q6.4@250.46,3072.97 ; v4(553.08,3027.53) 567.32,3041.77 Q5.4@567.32,3080.97
  Bottom Layer w40: v4(193,3068.28) 512.34,3068.28 v4(553.08,3027.53) 553.08,2991.66 R12.2@597.22,2947.53
NetC12_2: C12.2 D3.1 R13.2 | length 193.2
  Top Layer w40: C12.2@1958.93,1332.66 1958.93,1342.75 1988.46,1372.27 2001.4,1385.21 R13.2@2028.2,1385.21 2021.36,1392.05 D3.1@2021.36,1478.65
NetC13_1: C13.1 R10.1 | length 75.8
  Bottom Layer w60: R10.1@1303.02,3224.42 C13.1@1378.86,3224.42
NetC14_1: C14.1 R14.1 | length 108.4
  Bottom Layer w60: C14.1@2028.15,2056.17 2028.15,1951.93 R14.1@2031.09,1949
NetC15_1: C15.1 R15.1 | length 109.7
  Bottom Layer w60: C15.1@2359.78,2095.5 2364.7,2090.58 2461.18,2090.58 R15.1@2465.59,2086.18
NetC18_1: C18.1 D2.1 R23.2 | length 237
  Top Layer w24: C18.1@2399.65,1212.02 C18.1@2401.42,1210.25
  Top Layer w40: C18.1@2401.42,1210.25 2401.42,1367.7 2407.6,1373.88 D2.1@2407.6,1442.17
NetC25_1: C25.1 R59.1 | length 113
  Top Layer w10: R59.1@2780.2,1220.61 2794.93,1205.88 C25.1@2794.93,1113.69
NetC33_2: C33.2 C49.2 R46.2 U2.5 U2.8 | length 507.7
  Bottom Layer w40: R46.2@87.51,310.73 C33.2@87.51,196.95 87.82,197.27 127.73,197.27 128.59,198.13 C49.2@218.68,198.13 247.19,198.13 247.5,198.44 247.5,252.5 247.12,252.88 244.73,252.88 ; R46.2@96.65,312.38 98.31,310.73 165.14,310.73 189.56,335.15 189.56,351.09 193.16,354.69 244.73,354.69
NetC36_1: C36.1 Q7.4 Q8.4 R9.1 | length 728.8
  Top Layer w40: v4(3006.07,1057.76) 3020.24,1071.93 Q7.4@3060.7,1071.93 ; Q8.4@3262,1264.46 3290.46,1264.46 v4(3311,1285)
  Bottom Layer w40: v4(3006.07,1057.76) 3006.07,1086.57 2915.79,1176.85 R9.1@2915.79,1201.2 2964.02,1201.2 3047.82,1285 v4(3311,1285)
NetC50_2: C50.2 R48.1 R49.2 U2.2 | length 261.3
  Bottom Layer w10: U2.2@410.51,316.58 412.99,314.1 433.4,314.1 456.12,291.38 R48.1@501.51,291.38 501.51,243.2 477.03,218.72 R49.2@472.11,218.72
  Bottom Layer w14: R48.1@501.51,291.38 C50.2@573.69,291.38
NetC201_1: C201.1 R201.1 | length 79.9
  Top Layer w10: C201.1@2264.53,726.76 2274.6,736.82 R201.1@2274.6,802.45
NetC202_1: C202.1 R200.1 | length 73.2
  Top Layer w10: R200.1@2502.47,828.2 2502.47,804.99 2513.26,794.2 C202.1@2513.26,759.46
NetD2_2: D2.2 D3.2 R120.1 | length 614.8
  Top Layer w40: R120.1@1807.52,1460.93 1807.52,1468.18 1808.82,1469.48 1824.17,1469.48 1830.95,1476.26 D3.2@1903.01,1476.26 ; D3.2@1905.22,1478.65 1912.78,1486.21 1912.78,1516.42 1943.03,1546.68 2238.12,1546.68 2293.01,1491.79 2293.01,1447.33 D2.2@2298.6,1441.74
NetD4_1: D4.1 JP15.1 | length 127.5
  Top Layer w10: JP15.1@3774,525.56 D4.1@3890.91,525.56 D4.1@3898.4,533.05
NetD4_2: D4.2 R50.1 | length 155.1
  Top Layer w10: R50.1@3874.55,429 3874.55,462.5 3891.41,479.36 3935.25,479.36 3953.9,498.01 D4.2@3953.9,525.56
NetD5_2: D5.2 R51.1 | length 116.7
  Top Layer w10: D5.2@3828,639.01 3910.86,639.01 3924.56,652.71 R51.1@3924.56,653.6 ; R51.1@3928.67,649.49 R51.1@3938.26,659.08
NetD6_2: D6.2 R52.1 | length 99.7
  Top Layer w10: D6.2@3828,791.5 3915,791.5 R52.1@3924,800.5
NetD9_1: D9.1 D10.1 JP16.2 | length 374.7
  Bottom Layer w40: D10.1@75,642.03 170.47,642.03 195,617.5 JP16.2@195,522.5 197.5,520 340,520 D9.1@342.5,517.5
NetJP1_2: JP1.2 R64.2 | length 143.6
  Top Layer w10: R64.2@2597.98,875.35 2660.63,875.35 JP1.2@2717.87,932.59
NetJP4_1: JP4.1 R67.1 | length 121.9
  Top Layer w10: JP4.1@2090.97,828.29 2091.67,829 2145.06,829 2171.61,802.45 R67.1@2201.54,802.45
NetJP5_2: JP5.2 R34.2 | length 120.6
  Top Layer w10: JP5.2@1849.03,519.15 1882.85,485.33 R34.2@1955.63,485.33
NetJP6_2: JP6.2 R41.2 | length 140.4
  Top Layer w10: R41.2@2069.16,492.53 R41.2@2069.68,492 ; R41.2@2071.81,480.68 R41.2@2074.23,483.1 2074.23,452.87 2081.73,445.38 2093.81,445.38 2109.85,429.33 JP6.2@2109.85,374.06 ; JP6.2@2092.46,375.31 JP6.2@2096.22,379.07
NetJP9_1: JP9.1 R36.1 | length 125.2
  Top Layer w10: JP9.1@1868,792.25 1930.93,792.25 1948.26,774.91 1977.06,774.91 R36.1@1982.27,769.7 ; R36.1@1992.27,774.91 R36.1@1993.38,776.02
NetJP10_1: JP10.1 R66.1 | length 115.1
  Top Layer w10: R66.1@2363.26,943.64 2363.26,906.64 2383.92,885.98 2383.92,837.74 JP10.1@2384.34,837.31
NetJP12_1: JP12.1 R160.2 | length 131.4
  Top Layer w40: JP12.1@1476,1575 1562.61,1575 1580.03,1557.58 R160.2@1600.14,1557.58
NetJP12_3: JP12.3 R45.2 R300.1 | length 251.9
  Top Layer w40: R300.1@1356.46,1384.16 1363.7,1384.16 1372.87,1375 JP12.3@1476,1375 1476.49,1374.51 1476.49,1252.51 R45.2@1476.98,1252.02 ; JP12.3@1473.85,1378.65 JP12.3@1477.5,1375
NetJP14_1: JP14.1 R55.1 | length 102.4
  Top Layer w10: R55.1@3854.5,340 3858,336.5 JP14.1@3858,239
NetJP16_1: JP16.1 R46.1 | length 108.9
  Bottom Layer w40: R46.1@95,422.62 JP16.1@95,522.5 ; R46.1@96.65,422.62 103.33,422.62 R46.1@104.98,420.96
NetQ1_4: Q1.4 R8.1 | length 127.3
  Top Layer w40: v4(1398.39,2000.98) 1405.49,1993.87 1428.75,1970.62 1428.75,1941.45 Q1.4@1429.02,1941.19
  Bottom Layer w40: v4(1398.39,2000.98) 1398.39,1947.04 R8.1@1398.99,1946.44
NetQ2_4: Q2.4 R20.2 | length 142
  Top Layer w40: v4(1473.85,2041.95) 1510.05,2041.95 1528.01,2024 Q2.4@1528.01,1999.99
  Bottom Layer w40: v4(1473.85,2041.95) 1479.53,2047.63 R20.2@1479.53,2096
NetQ3_4: Q3.4 R3.1 | length 88.3
  Top Layer w40: v4(2877.96,1703) 2900.8,1725.84 2900.8,1739.26 Q3.4@2901.07,1738.98
  Bottom Layer w40: R3.1@2835.76,1703 v4(2877.96,1703)
NetQ4_4: Q4.4 R17.2 | length 115
  Top Layer w40: Q4.4@2641.35,2077.26 2641.35,2113.37 2648,2120.02 v4(2648,2125)
  Bottom Layer w40: v4(2648,2125) 2649.5,2123.5 R17.2@2649.5,2061.1
P_OUT: C17.1 C28.2 C29.2 C40.2 C45.2 C46.2 C53.2 C54.2 C56.2 C57.2 C82.1 C152.1 C504.2 C505.2 C514.2 C515.2 D8.3 Q3.5-6-7-8 Q8.5-6-7-8 R22.1 R24.2 R1002.2 R1003.2 R1004.1 R1005.1 TP41.1 | length 1539.1
  Top Layer w10: R22.1@2548.68,1147.83 2548.68,1144.83 2558.44,1135.06 2584.68,1135.06 2599.03,1120.71 v1(2602.82,1120.71) ; TP41.1@2872.64,1593.12 2970.66,1593.12 2972.49,1594.96 ; R24.2@3458.48,1577.28 3458.48,1579.45 3473.17,1594.14 v1(3506.49,1594.14)
  Layer 3 w10: v1(2602.82,1120.71) 2606.61,1120.71 2614.87,1112.45 3332.47,1112.45 3538.55,1318.53 3538.55,1564.91 3509.32,1594.14 v1(3506.49,1594.14)
  other v1: 3333.28,1332.36 3333.29,1363.83 3290.46,1576.89 3356.57,1576.89 3290.46,1616.89 3356.57,1616.89 3290.46,1656.89 3356.57,1656.89 3290.46,1696.89 3356.57,1696.89 3290.46,1736.89 3356.57,1736.89 3290.46,1776.89 3356.57,1776.89 3518.25,1897.97 3395.91,1900.65 3395.91,1937.97 3518.25,1937.97 3071.37,1955.64 3395.91,1977.97 3518.25,1977.97 3071.37,1995.64 3251.56,2011.79 3029.52,2029.05 3070.07,2029.05 3520.46,2033.37 3488.81,2034.61 3251.56,2042.39 3031.48,2061 3070.07,2069.05 3481.96,2073.37 3520.46,2073.37 3251.56,2079.72 3052.82,2103 3252.16,2113.37 3481.96,2113.37 3520.46,2113.37 3051.69,2141.75 3518.25,2172 3070.07,2176.98 3392.97,2185.8 3027,2188.04 3518.25,2212 3053.82,2214.91 3045.97,2249.86 3076.42,2249.86 3172.82,2252.04 3209,2252 3320,2252.04 3349.08,2252 3518.25,2252 3051.93,2281 3172.82,2281 3208.14,2281 3320,2281 3349.08,2281 3518.25,2288 3462.09,2291 2970.78,2309.84 3185.59,2309.84 3332.78,2317.94 3518.25,2317.94 3462.09,2322.94 3185.59,2346.27 2972.49,2347.31 3333.29,2347.31 3473.17,2347.31 3518.25,2347.31 3052.82,2359
  other v2: 3128.14,1331.02 3168.14,1331.02 3208.14,1331.02 3248.14,1331.02 3128.14,1371.02 3168.14,1371.02 3208.14,1371.02 3248.14,1371.02 3128.14,1411.02 3168.14,1411.02 3208.14,1411.02 3248.14,1411.02 3128.14,1451.02 3168.14,1451.02 3208.14,1451.02 3248.14,1451.02 2971.93,1765.31 3011.93,1765.31 3051.93,1765.31 3091.93,1765.31 2971.93,1805.31 3011.93,1805.31 3051.93,1805.31 3091.93,1805.31 2971.93,1845.31 3011.93,1845.31 3051.93,1845.31 3091.93,1845.31 2971.93,1885.31 3011.93,1885.31 3051.93,1885.31 3091.93,1885.31
PGND: C2.1 C3.2 C4.2 C5.1 C6.2 C7.1 C8.1 C10.2 C11.2 C13.2 C14.2 C15.2 C16.2 C17.2 C19.2 C20.2 C21.2 C22.2 C23.2 C24.2 C26.2 C28.1 C29.1 C31.2 C32.2 C33.1 C38.1 C39.1 C40.1 C42.1 C43.2 C44.1 C45.1 C46.1 C48.2 C49.1 C53.1 C54.1 C56.1 C57.1 C60.2 C63.2 C70.1 C74.2 C77.2 C78.2 C80.2 C81.2 C82.2 C150.1 C151.2 C152.2 C200.2 C201.2 C202.2 C500.1 C501.1 C502.1 C503.1 C504.1 C505.1 C506.1 C507.1 C508.1 C509.1 C510.1 C511.1 C512.1 C513.1 C514.1 C515.1 C516.1 C517.1 C518.1 C519.1 D7.1 D7.2 J1.1 J2.2 J3.2 J4.6 J5.1 J6.1 J7.2 J7.3 J7.6 J7.7 J8.2 J8.3 JP3.2 JP4.2 JP7.2 JP8.2 JP9.2 JP10.2 JP11.2 JP13.2 pad.Pad2 Q2.1 Q2.2 Q2.3 Q4.1 Q4.2 Q4.3 R30.1 R32.1 R41.1 R49.1 R65.1 R151.1 R152.1 R153.1 R154.1 R400.1 R401.1 TP35.1 TP36.1 TP37.1 TP38.1 TP39.1 TP40.1 TP47.1 U1.22 U1.37 U2.4 U2.9 | length 160.8
  Top Layer w9.84: U1.37@2150.02,1115.24 2179.55,1144.77 U1.22@2179.55,1209.73 2179.55,1222.92 2179.55,1248.99 2187.34,1256.78 v3(2187.34,1260.61)
  other v1: 750.05,92.49 790.05,92.49 671,111 669,150 750.1,210.57 790.1,210.57 4056,326.08 4017.24,327.17 341.68,840.79 381.44,841.87 4332,846.95 161.08,854.25 200,854 240,854 280,854 341.68,880.79 381.68,880.79 160,894 200,894 240,894 280,894 4332,928 221,943 261,943 221,983 261,983 717,1054.17 814,1054.17 653.17,1080.32 3810,1138 3874.55,1167.22 827,1831 861,1831 582.78,1852.53 612.13,1852.53 827,1864.58 3624.5,1888.79 3753.98,1889.68 3789.5,1890.51 3847,1894 3889,1894 570,1896.85 3930.5,1897.97 698.26,1914.53 3624.5,1928.79 3753.98,1929.68 3789.5,1930.51 3931,1933.91 3624.5,1968.79 3753.98,1969.68 3789.5,1970.51 3930.5,1974 596.39,1994.15 3624.5,2008.79 3753.98,2009.68 3789.5,2010.51 3931,2011.79 570,2025 610.82,2025 653,2030 2860,2061 2833,2069.05 841.94,2092.91 2834.08,2103 3798.51,2129.84 3762.51,2130.65 827,2132 2834.08,2136.9 489,2144.58 522,2144.58 3614.74,2148.04 1455.2,2156.57 827,2162.53 2833,2165 3798,2165 3762.51,2170.65 488.17,2176.43 1494.53,2185.92 3614.74,2188.04 512.32,2190.47 2863.18,2192.2 2833,2195.61 827.58,2200.38 3798.51,2209.84 3762.51,2210.65 1529.29,2212.75 1493.98,2218.09 3614.74,2228.04 2833,2232.93 3886.84,2247.57 3926.84,2247.57 760.44,2249.13 3798.51,2249.84 1493.11,2251.26 3762.51,2250.65 1529.29,2265.72 3614.74,2268.04 512.32,2270.36 484.51,2273.46 2833,2272.93 848.89,2277.82 1491.86,2284.37 760.44,2286.31 1416.24,2286.31 1446.83,2285.7 2833,2304.47 484.51,2304.97 510.85,2304.97 3614.74,2308.04 1529.29,2314.98 848.11,2317.69 760.95,2319.56 484.51,2333.64 510.85,2333.64 2833,2346.27 760.44,2355.79 691,2364 3884.42,2368.57 3924.42,2368.57 760.95,2389.33 2920.19,2389.31 2833,2389.53 3847,2402 691,2404 760.95,2420 954,2420 1103.95,2420 1247.74,2423.43 1424.91,2425.23 1460.21,2425.23 1495.51,2425.23 1388.41,2425.79 3041,2430 3329,2443.4 3847,2443.4 691,2444 3188,2444.51 1103.95,2447.39 3470.86,2449.01 954,2450 1246,2454 1387.59,2454 1424.11,2456 1460.57,2456 1497.03,2456 1533.48,2456 3041.1,2466.96 488.17,2472 3188,2476 3329,2476 3471.04,2478.67 3785.5,2484.51 510.5,2490 2921.1,2510.73 2961.1,2510.73 3001.1,2510.73 3041.1,2510.73 3081.1,2510.73 686.02,2512.81 3398.51,2513.5 3518.51,2513.5 3558.51,2513.5 3427.43,2518.5 3467.43,2518.5 903.95,2521.32 943.95,2521.32 983.95,2521.32 1023.95,2521.32 1063.95,2521.32 1103.95,2521.32 1152.48,2521.32 1192.48,2521.32 1232.48,2521.32 1272.48,2521.32 1312.48,2521.32 1352.48,2521.32 3785.5,2524.51 3209,2538 3249,2538 3289,2538 3329,2538 3369,2538 686.02,2552.81 983.95,2561.32 1023.95,2561.32 1063.95,2561.32 1103.95,2561.32 1152.48,2561.32 1192.48,2561.32 1232.48,2561.32 1272.48,2561.32 1312.48,2561.32 1352.48,2561.32 2921.1,2579.72 2961.1,2579.72 3001.1,2579.72 3041.1,2579.72 3081.1,2579.72 3189.08,2579.72 3229.08,2579.72 3269.08,2579.72 3309.08,2579.72 3349.08,2579.72 691,2585 3539,2603 3678,2603 3541,2642 3678,2642 3432,2657 3473.17,2657 1055.62,2665.32 1095.62,2665.32 3680,2681.49 3595.35,2683.62 3634.69,2683.62 3430,2694 3470.86,2694 3680,2720.49 3594.69,2721 3634.69,2721 3027,2731.57 3229.08,2731.57 3332.78,2731.57 1462.34,2815.25 2659.52,2940.97 2659.52,2970.06 1460,3048 1500,3048 1540,3048 1580,3048 2694.82,3081.91 2734.82,3081.91 2774.82,3081.91 2814.82,3081.91 1460,3088 1500,3088 1540,3088 1580,3088 2694.82,3121.91 2734.82,3121.91 2774.82,3121.91 2814.82,3121.91 1569,3136 1609,3136 1649,3136 1689,3136 2694.82,3170.91 2734.82,3170.91 2774.82,3170.91 2814.82,3170.91 1569,3176 1609,3176 1649,3176 1689,3176 2694.82,3210.91 2734.82,3210.91 2774.82,3210.91 2814.82,3210.91 1830.82,3250.91 2518.82,3260.91
  other v2: 308.19,284.31 348.19,284.31 308.19,324.31 348.19,324.31
  other v3: 2882.74,358.87 1704.41,367.5 1716.92,409.78 2597.98,418.52 1769.3,436.3 1792.67,451.42 2597.98,463.57 2211.07,485.33 2433.21,512 2564.88,512 2599.5,519.15 2034.6,523.55 2164.79,523.55 2124.67,548.91 2524.02,574.42 2088.5,580.52 2553.44,580.52 1759.53,605.1 1788.66,605.1 1818,605.1 2077.22,613.32 2548.68,613.71 2447.19,644.7 2090.97,651.52 2125.05,651.96 2153.51,651.96 2476.55,653.67 2515.4,653.67 2550.21,676.35 2457.37,685.1 1823.49,694.66 1760.8,695.54 2553.44,705.17 2140.18,706.32 1769.89,721.7 1799.03,721.7 1830.81,723 1863.1,723 1615.29,726.76 1644.93,726.76 1676.77,726.76 2153.51,735.89 2431.88,737.31 1754.48,745.53 1803.19,751.27 2124.67,762.9 2153.51,762.9 2454.03,762.9 2423,769.84 2454.03,797.25 1888.66,851.36 1912.24,875.99 1823.49,876.92 1768,879.91 1797.33,880.55 1967.91,880.55 1993.38,880.55 1818,906.64 1849.03,906.64 2576.24,929.21 2616.61,931.71 2621.69,994.22 2641.73,1020.76 4122,1036 1809.59,1087.65 1803.19,1113.23 1617.48,1118.41 1644.93,1125.01 1596.8,1135.06 4226,1142 4129,1145 1381.49,1255.94 2646.54,1256.78 2677.99,1257.45 2616.61,1260.09 1381.49,1288.14 2641.73,1289.63 1797.33,1307.31 1772.65,1308.11 2650.9,1321.99 2677.99,1332.66 2568.99,1387.84 2152.65,1400.63 2540.26,1400.63 2158.24,1427.19 2522.5,1434.31 2135.72,1442.12 2147.82,1463.96 2135.65,1490.64
  other v5: 2104.35,1054.22 2150.02,1054.22 2195.69,1054.22 2069.31,1091.03 2104.35,1091.03 2150.02,1091.03 2195.69,1091.03 2230.73,1091.03 2069.31,1139.46 2104.35,1139.46 2150.02,1139.46 2195.69,1139.46 2230.73,1139.46 2104.35,1176.27 2150.02,1176.27 2195.69,1176.27
PP5V: J8.1 R68.1 | length 2260
  Layer 3 w40: v4(957.5,84.29) 3104.29,84.29 J8.1@3133,113
  Bottom Layer w40: R68.1@895.63,58.4 931.6,58.4 v4(957.5,84.29)
REGN: C22.1 JP5.1 R160.1 TP1.1 U1.24 | length 2321.4
  Top Layer w9.84: v3(2137.23,1293.82) 2137.23,1289.99 2140.18,1287.04 U1.24@2140.18,1209.73
  Top Layer w10: TP1.1@1631.64,367.5 1710.2,446.06 1741.6,446.06 1747.46,451.92 1747.46,517.58 JP5.1@1749.03,519.15
  Top Layer w24: C22.1@2110.65,1327.79 2115.57,1327.79 2137.23,1306.14 v3(2137.23,1293.82)
  Top Layer w40: R160.1@1663.13,1557.58 1728.09,1557.58 v4(1764.67,1594.16)
  Layer 4 w24: JP5.1@1749.03,519.15 1716.74,551.44 1716.74,737.02 1716.63,737.13 1716.63,876.4 1738.4,898.17 1738.4,1321.72 1771.15,1354.46 2054.22,1354.46 2086.7,1321.99 2129.61,1321.99 2137.23,1329.6 ; 2131.55,1348.79 2137.23,1343.11 2137.23,1329.6 ; v3@2135.99,1293.82 v3(2137.23,1293.82) 2137.23,1329.6
  Layer 4 w40: v4(1764.67,1594.16) 1764.67,1477.33 1825.41,1416.59 2069.42,1416.59 2131.55,1354.46 2131.55,1348.79
SCL: J4.9 J5.2 J8.4 R53.1 TP33.1 U1.1 | length 4075.8
  Top Layer w9.84: v1(2051.73,961.66) 2053.22,963.14 2053.22,988.42 2061.44,996.64 U1.1@2061.44,1020.76
  Top Layer w10: TP33.1@3938.26,1085.1 3941.84,1081.52 4000.02,1081.52 4090,991.53 4090,702 4106.9,685.1 J4.9@4189,685.1 J4.9@4183.9,680 ; J5.2@4139,233.41 4178,272.41 R53.1@4178,369.9
  Layer 3 w10: v1(2051.73,961.66) 2051.62,961.66 2024.89,934.92 2024.89,574.38 2167.5,431.77 2167.5,300.02 2174.7,292.82 3233,292.82 ; J8.4@3233,213 3233,292.82 ; J4.9@4189,685.1 4189,520.11 4139.01,470.12 4139.01,245 4091.2,292.82 3233,292.82
SDA: J4.10 J5.3 J8.6 R54.1 TP34.1 U1.2 | length 5807.2
  Top Layer w9.84: v1(2055.51,927.58) 2077.04,949.12 2081.12,953.2 2081.12,1012.14 U1.2@2081.12,1020.76
  Top Layer w10: TP34.1@3942,1235 4332,1235 4359,1208 4359,755.1 J4.10@4289,685.1 ; J5.3@4239,233.41 4327.97,322.37 4347.64,322.37 4353.5,328.23 R54.1@4353.5,371
  Layer 3 w10: v1(2055.51,927.58) 2055.51,871.67 2044.73,860.89 2044.73,582.6 2187.34,439.99 2187.34,319.87 2194.55,312.66 2919.44,312.66 2920.79,314.01 3645.69,314.01 3671.02,339.34 3749.75,339.34 4145,734.6 4239.5,734.6 J4.10@4289,685.1 4289,510.12 4239.01,460.13 J5.3@4239.01,245 ; J8.6@3333,213 3333,262.91 3343.06,272.97 3922.14,272.97 3948.08,247.04 3948.08,205.28 3991.36,162 4226.92,162 4239,174.08 J5.3@4239,233.41
SRN: C23.1 C35.2 R25.2 TP23.1 U1.13 | length 962.9
  Top Layer w9.84: U1.13@2264.2,1085.72 2311.14,1085.72 2311.22,1085.64
  Top Layer w10: 2311.22,1085.64 2317.1,1079.76 2364.22,1079.76 2383.38,1060.6 2419.96,1060.6 2429.24,1069.88 R25.2@2491.15,1069.88 2491.15,1033.59 C23.1@2522.67,1002.07 ; v1(2473.69,1014.15) 2493.08,994.76 C23.1@2520.68,994.76
  Layer 4 w10: v1(2473.69,1014.15) 2473.69,1217.09 2709.64,1453.04 2758.67,1453.04 TP23.1@2758.79,1452.92
SRP: C21.1 C35.1 R22.2 TP22.1 U1.14 | length 699.3
  Top Layer w9.84: U1.14@2264.2,1105.4 2319.41,1105.4 2325.27,1099.54
  Top Layer w10: 2325.32,1099.6 2362.37,1099.6 2378.02,1115.24 2411.61,1115.24 C35.1@2419.96,1123.59 ; C35.1@2431.88,1122.53 2465.93,1122.53 2476.55,1133.14 2479.86,1133.14 2489.63,1142.91 R22.2@2489.63,1147.83 2489.63,1213.01 C21.1@2492.68,1216.07 2489.63,1219.12 2489.63,1266.69 2579.46,1266.69 2616.61,1303.84 2616.61,1416.62 2598.13,1435.11 TP22.1@2598.13,1448.26 ; TP22.1@2612.07,1452.92 2618.12,1446.87 TP22.1@2618.12,1482.6
STAT1: JP15.2 TP29.1 U1.4 | length 2200.9
  Top Layer w9.84: v1@2120.49,926.66 U1.4@2120.49,1020.76
  Top Layer w10: JP15.2@3674,525.56 3674,583.54 3699.5,609.04 TP29.1@3699.5,664.6
  Layer 3 w10: v1(2114.34,916.68) 2117.02,914 2117.02,903.33 2135.72,884.63 2138.82,884.63 2183.56,839.9 2183.56,568.54 2211.1,541 2552.31,541 2560.22,548.91 3016.59,548.91 3132.28,664.6 TP29.1@3699.5,664.6
STAT2: D5.1 TP31.1 U1.5 | length 2082
  Top Layer w9.84: U1.5@2140.18,1020.76 2140.18,948.56 2145.1,943.64 2145.1,924.44 2145.11,914.42 v1(2147.82,911.71)
  Top Layer w10: TP31.1@3698,791.01 TP31.1@3698,800.5 3796.5,702 D5.1@3828,702
  Layer 3 w10: v1(2147.82,911.71) 2147.82,911.29 2244,815.11 2244,685.27 2249.86,679.42 2411.74,679.42 2442.8,710.47 2443,710.47 2468.43,735.89 2568.74,735.89 2588.59,716.05 3539.85,716.05 3624.47,800.68 3697.82,800.68 TP31.1@3698,800.5
SW1: C12.1 D7.3 L1.1 L2.1 Q1.1 Q1.2 Q1.3 Q2.5-6-7-8 R14.2 TP18.1 U1.28 | length 1793.9
  Top Layer w10: L1.1@1859.96,2176.98 1924,2241.02 1924,2456 2051.01,2583.01 TP18.1@2051.01,2637
  Top Layer w20: v3@1985.42,1227.98 2003.67,1209.73 2056.36,1209.73
  Top Layer w40: C12.1@1958.93,1276.66 1988.14,1247.45 v3@1988.14,1231.77
  Layer 3 w40: v4(1502.02,1916.64) 1502.02,1929.14 1561.52,1988.64 1704.07,1988.64 1953.73,1738.98 1953.73,1372.76 1955.16,1371.33 1955.16,1251.41 1978.59,1227.98 v3(1984.34,1227.98)
  other v2: 1550.07,1801.2 1590.07,1801.2 1630.07,1801.2 1670.07,1801.2 1550.07,1841.2 1590.07,1841.2 1630.07,1841.2 1670.07,1841.2 1550.07,1881.2 1590.07,1881.2 1630.07,1881.2 1670.07,1881.2 1550.07,1921.2 1590.07,1921.2 1630.07,1921.2 1670.07,1921.2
